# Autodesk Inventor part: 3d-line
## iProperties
Created: 2005-04
Part Number: 3d-line
Document SubType Name: Modeling
Designer: CADCIM
Density: 1 g/cm^3
Author: CADCIM
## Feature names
1. Extrusion1
2. Hole1
3. Hole2
